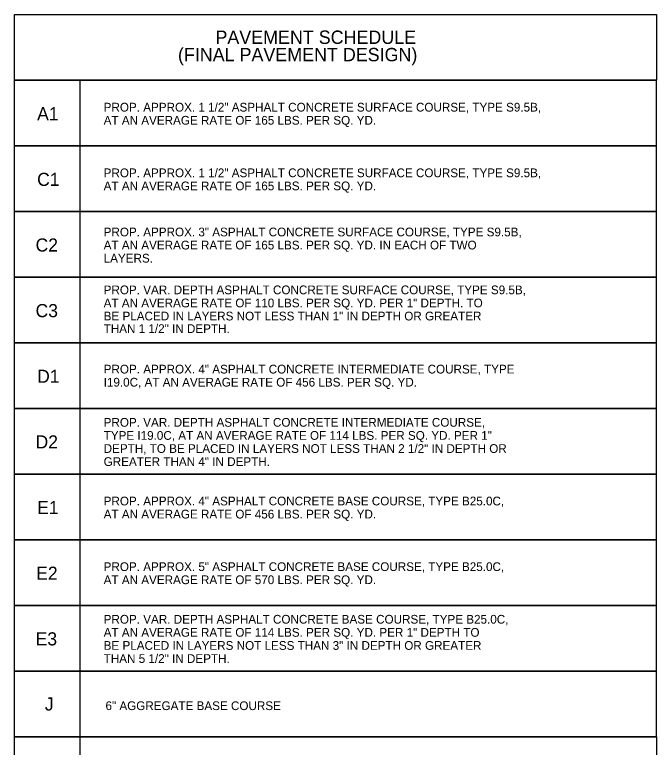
# Model space of a CAD drawing. Extents: x 1901670 to 1902225, y 193498 to 194278.
# Drawn here: x 1902187.77 to 1902225.13, y 194156.63 to 194199.27 of the extents above; entities that cross this region are included whole.
import ezdxf

# ---------------------------------------------------------------- set-up
doc = ezdxf.new("R2010")
doc.units = 0
for name, color, linetype in [('Old_Level_19', 7, 'Continuous'), ('Old_Level_21', 7, 'Continuous'), ('Prop Pavement Schedule Description CELL', 7, 'Continuous')]:
    doc.layers.add(name, color=color, linetype=linetype)

msp = doc.modelspace()

# ---------------------------------------------------------------- linework, layer by layer
at = {"layer": 'Old_Level_19'}
msp.add_lwpolyline([(1902187.769, 194199.272), (1902225.125, 194199.272), (1902225.125, 194195.452), (1902187.769, 194195.452)], close=True, dxfattribs=at)
for points in [[(1902191.589, 194191.632), (1902187.769, 194191.632), (1902187.769, 194195.452), (1902225.124, 194195.452), (1902225.124, 194191.632), (1902191.589, 194191.632), (1902191.589, 194195.452)], [(1902191.589, 194187.811), (1902187.769, 194187.811), (1902187.769, 194191.632), (1902225.124, 194191.632), (1902225.124, 194187.811), (1902191.589, 194187.811), (1902191.589, 194191.632)], [(1902191.589, 194183.991), (1902187.769, 194183.991), (1902187.769, 194187.811), (1902225.124, 194187.811), (1902225.124, 194183.991), (1902191.589, 194183.991), (1902191.589, 194187.811)], [(1902191.589, 194180.17), (1902187.769, 194180.17), (1902187.769, 194183.991), (1902225.124, 194183.991), (1902225.124, 194180.17), (1902191.589, 194180.17), (1902191.589, 194183.991)], [(1902191.589, 194176.35), (1902187.769, 194176.35), (1902187.769, 194180.17), (1902225.124, 194180.17), (1902225.124, 194176.35), (1902191.589, 194176.35), (1902191.589, 194180.17)], [(1902191.589, 194172.53), (1902187.769, 194172.53), (1902187.769, 194176.35), (1902225.124, 194176.35), (1902225.124, 194172.53), (1902191.589, 194172.53), (1902191.589, 194176.35)], [(1902191.589, 194168.709), (1902187.769, 194168.709), (1902187.769, 194172.53), (1902225.124, 194172.53), (1902225.124, 194168.709), (1902191.589, 194168.709), (1902191.589, 194172.53)], [(1902191.589, 194164.889), (1902187.769, 194164.889), (1902187.769, 194168.709), (1902225.124, 194168.709), (1902225.124, 194164.889), (1902191.589, 194164.889), (1902191.589, 194168.709)], [(1902191.589, 194161.068), (1902187.769, 194161.068), (1902187.769, 194164.889), (1902225.124, 194164.889), (1902225.124, 194161.068), (1902191.589, 194161.068), (1902191.589, 194164.889)], [(1902191.589, 194157.248), (1902187.769, 194157.248), (1902187.769, 194161.068), (1902225.124, 194161.068), (1902225.124, 194157.248), (1902191.589, 194157.248), (1902191.589, 194161.068)]]:
    msp.add_lwpolyline(points, dxfattribs=at)
at = {"layer": 'Prop Pavement Schedule Description CELL'}
msp.add_lwpolyline([(1902191.589, 194153.428), (1902187.769, 194153.428), (1902187.769, 194157.248), (1902225.125, 194157.248), (1902225.125, 194153.428), (1902191.589, 194153.428), (1902191.589, 194157.248)], dxfattribs=at)

# ---------------------------------------------------------------- texts
at = {"layer": 'Old_Level_21'}
for s, height, p in [('PAVEMENT SCHEDULE', 0.77824, (1902199.458, 194197.569)), ('(FINAL PAVEMENT DESIGN)', 0.77824, (1902197.277, 194196.558)), ('PROP. APPROX. 1 1/2" ASPHALT CONCRETE SURFACE COURSE, TYPE S9.5B,', 0.50819, (1902192.951, 194193.632)), ('A1', 0.7627, (1902189.078, 194193.126)), ('AT AN AVERAGE RATE OF 165 LBS. PER SQ. YD.', 0.50819, (1902192.951, 194192.87)), ('PROP. APPROX. 1 1/2" ASPHALT CONCRETE SURFACE COURSE, TYPE S9.5B,', 0.50819, (1902192.951, 194189.812)), ('C1', 0.7627, (1902189.078, 194189.305)), ('AT AN AVERAGE RATE OF 165 LBS. PER SQ. YD.', 0.50819, (1902192.951, 194189.05)), ('PROP. APPROX. 3" ASPHALT CONCRETE SURFACE COURSE, TYPE S9.5B,', 0.50819, (1902192.951, 194186.369)), ('C2', 0.7627, (1902188.987, 194185.485)), ('AT AN AVERAGE RATE OF 165 LBS. PER SQ. YD. IN EACH OF TWO', 0.50819, (1902192.951, 194185.607)), ('LAYERS.', 0.5082, (1902192.951, 194184.845)), ('PROP. VAR. DEPTH ASPHALT CONCRETE SURFACE COURSE, TYPE S9.5B,', 0.50819, (1902192.951, 194183)), ('AT AN AVERAGE RATE OF 110 LBS. PER SQ. YD. PER 1" DEPTH. TO', 0.50819, (1902192.951, 194182.238)), ('C3', 0.7627, (1902188.987, 194181.665)), ('BE PLACED IN LAYERS NOT LESS THAN 1" IN DEPTH OR GREATER', 0.50819, (1902192.951, 194181.476)), ('THAN 1 1/2" IN DEPTH.', 0.50819, (1902192.951, 194180.743)), ('PROP. APPROX. 4" ASPHALT CONCRETE INTERMEDIATE COURSE, TYPE', 0.50819, (1902192.951, 194178.387)), ('D1', 0.7627, (1902189.078, 194177.844)), ('I19.0C, AT AN AVERAGE RATE OF 456 LBS. PER SQ. YD.', 0.50819, (1902192.951, 194177.625)), ('PROP. VAR. DEPTH ASPHALT CONCRETE INTERMEDIATE COURSE,', 0.50819, (1902192.951, 194175.289)), ('TYPE I19.0C, AT AN AVERAGE RATE OF 114 LBS. PER SQ. YD. PER 1" ', 0.50819, (1902192.951, 194174.527)), ('D2', 0.7627, (1902188.987, 194174.024)), ('DEPTH, TO BE PLACED IN LAYERS NOT LESS THAN 2 1/2" IN DEPTH OR', 0.50819, (1902192.951, 194173.765)), ('GREATER THAN 4" IN DEPTH.', 0.50819, (1902192.951, 194173.004)), ('PROP. APPROX. 4" ASPHALT CONCRETE BASE COURSE, TYPE B25.0C,', 0.50819, (1902192.951, 194170.71)), ('E1', 0.7627, (1902189.078, 194170.203)), ('AT AN AVERAGE RATE OF 456 LBS. PER SQ. YD.', 0.50819, (1902192.951, 194169.948)), ('PROP. APPROX. 5" ASPHALT CONCRETE BASE COURSE, TYPE B25.0C,', 0.50819, (1902192.951, 194166.89)), ('E2', 0.7627, (1902189.024, 194166.382)), ('AT AN AVERAGE RATE OF 570 LBS. PER SQ. YD.', 0.50819, (1902192.951, 194166.128)), ('PROP. VAR. DEPTH ASPHALT CONCRETE BASE COURSE, TYPE B25.0C,', 0.50819, (1902192.951, 194163.828)), ('AT AN AVERAGE RATE OF 114 LBS. PER SQ. YD. PER 1" DEPTH TO', 0.50819, (1902192.951, 194163.066)), ('E3', 0.7627, (1902188.992, 194162.562)), ('BE PLACED IN LAYERS NOT LESS THAN 3" IN DEPTH OR GREATER', 0.50819, (1902192.951, 194162.304)), ('THAN 5 1/2" IN DEPTH.', 0.50819, (1902192.951, 194161.542)), ('J', 0.763, (1902189.526, 194158.77)), ('6" AGGREGATE BASE COURSE', 0.50819, (1902193.058, 194158.797))]:
    msp.add_text(s, height=height, dxfattribs=at).set_placement(p)

doc.saveas('drawing.dxf')
